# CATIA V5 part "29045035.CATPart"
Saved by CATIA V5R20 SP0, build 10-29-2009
Part number: 29045035
Definition: NONE
Nomenclature: 29045035
Source: Unknown
Description: 29045035
Bounding box of the stored display mesh (mm): x -17.5 to 44.548, y -36.5 to 71.048, z -26.5 to 26.5
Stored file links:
  C:\Users\Utente\Desktop\IO LAVORO\3D X SITO CF\X SITO\PLASTICA\RF1\29045035.CATPart
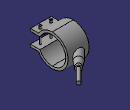
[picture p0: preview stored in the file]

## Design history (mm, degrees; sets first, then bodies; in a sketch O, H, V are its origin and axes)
Body1 "29045035" (main body)
  Solid1: solid without history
